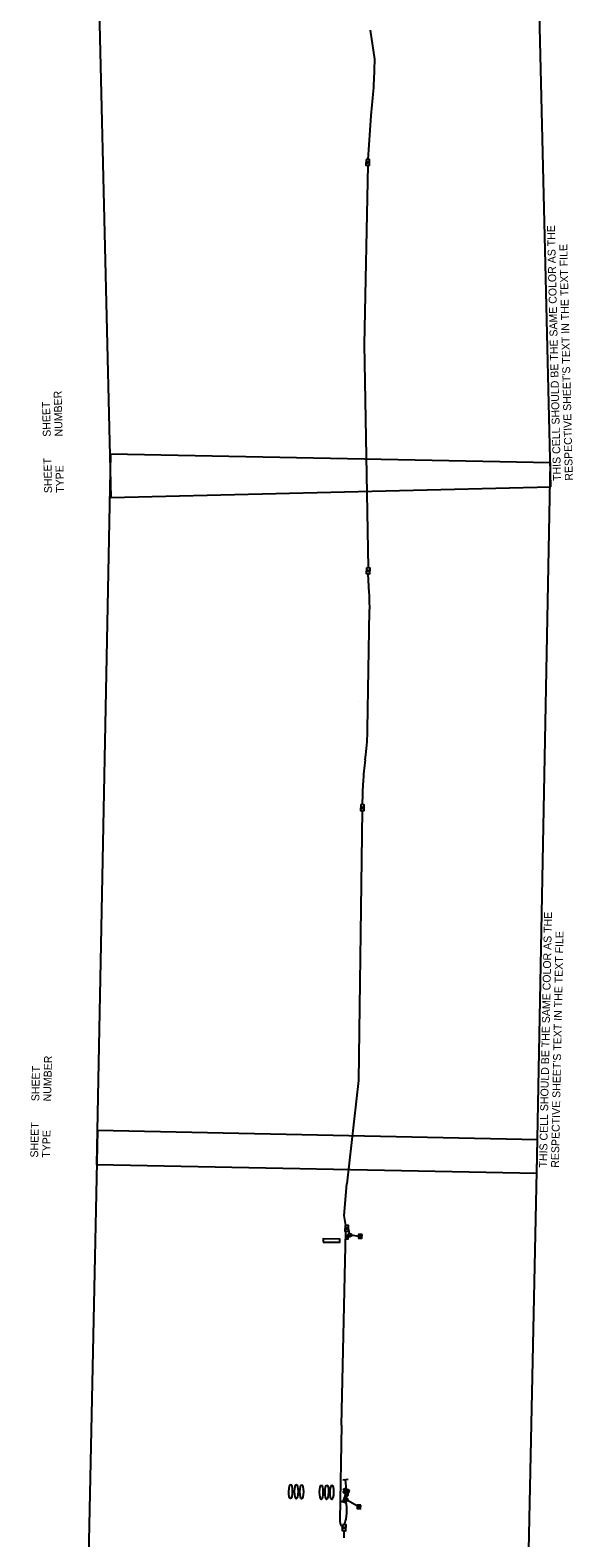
# Model space of a CAD drawing. Extents: x 601462 to 605493, y 331960 to 402715.
# Drawn here: x 603678 to 604880, y 344593 to 347935 of the extents above; entities that cross this region are included whole.
import ezdxf

# ---------------------------------------------------------------- set-up
doc = ezdxf.new("R2010")
doc.units = 0
for name, color, linetype in [('E_FTMS', 7, 'Continuous'), ('P_FTMS', 7, 'Continuous'), ('P_FTMSConduit', 7, 'Continuous'), ('P_MISC_TXT_2A (Construction)', 7, 'Continuous'), ('P_MISC_TXT_2B (Construction)', 7, 'Continuous')]:
    doc.layers.add(name, color=color, linetype=linetype)

# ---------------------------------------------------------------- blocks, each defined once
blk = doc.blocks.new('FMD')
at = {"layer": 'P_FTMS'}
for p, q in [((17, 18), (-17, 18)), ((-16, 16), (-16, 18)), ((16, 16), (-16, 16)), ((-15, 15), (-15, 20)), ((15, 19), (-15, 19)), ((15, 15), (-15, 15)), ((14, 20), (-14, 20)), ((13, 22), (-13, 22)), ((-13, 13), (-13, 21)), ((13, 13), (-13, 13)), ((-12, 12), (-12, 23)), ((12, 12), (-12, 12)), ((11, 23), (-11, 23)), ((10, 25), (-10, 25)), ((-10, 10), (-10, 24)), ((10, 10), (-10, 10)), ((-9, 9), (-9, 26)), ((9, 9), (-9, 9)), ((8, 26), (-8, 26)), ((7, 28), (-7, 28)), ((-7, 7), (-7, 27)), ((7, 7), (-7, 7)), ((-6, 6), (-6, 29)), ((6, 6), (-6, 6)), ((5, 29), (-5, 29)), ((4, 31), (-4, 31)), ((-4, 4), (-4, 30)), ((4, 4), (-4, 4)), ((-3, 3), (-3, 32)), ((3, 3), (-3, 3)), ((2, 32), (-2, 32)), ((1, 34), (-1, 34)), ((-1, 1), (-1, 33)), ((1, 1), (-1, 1)), ((0, 0), (0, 34)), ((1, 1), (1, 33)), ((3, 3), (3, 32)), ((4, 4), (4, 30)), ((6, 6), (6, 29)), ((7, 7), (7, 27)), ((9, 9), (9, 26)), ((10, 10), (10, 24)), ((12, 12), (12, 23)), ((13, 13), (13, 21)), ((15, 15), (15, 20)), ((16, 16), (16, 18))]:
    blk.add_line(p, q, dxfattribs=at)
blk.add_lwpolyline([(-17, 17), (0, 34), (17, 17), (0, 0)], close=True, dxfattribs=at)
blk = doc.blocks.new('FMB')
at = {"layer": 'P_FTMS'}
for p, q in [((24, -24), (-24, 24)), ((-24, -24), (24, 24))]:
    blk.add_line(p, q, dxfattribs=at)
blk.add_lwpolyline([(24, -24), (24, 24), (-24, 24), (-24, -24)], close=True, dxfattribs=at)
blk = doc.blocks.new('_U218')
at = {"layer": 'P_FTMS'}
for points in [[(-15, -7), (7, -15), (0, 0)], [(15, 7), (-7, 15), (0, 0)]]:
    blk.add_lwpolyline(points, close=True, dxfattribs=at)
at = {"layer": 'P_FTMS', "xscale": 0.4713263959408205, "yscale": 0.4713263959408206, "rotation": 70.39802054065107}
blk.add_blockref('FMB', (0, 0), dxfattribs=at)
blk = doc.blocks.new('FMB_1')
at = {"layer": 'P_FTMS'}
for p, q in [((24, -24), (-24, 24)), ((-24, -24), (24, 24))]:
    blk.add_line(p, q, dxfattribs=at)
blk.add_lwpolyline([(24, -24), (24, 24), (-24, 24), (-24, -24)], close=True, dxfattribs=at)
blk = doc.blocks.new('FTMS_FCV')
at = {"layer": 'P_FTMS'}
blk.add_line((13, 16), (1, -22), dxfattribs=at)
blk.add_lwpolyline([(39, 24), (-39, 24), (-39, -24), (39, -24)], close=True, dxfattribs=at)
blk.add_lwpolyline([(-12, 16), (1, -22)], dxfattribs=at)
blk = doc.blocks.new('_U256')
at = {"layer": 'P_FTMS'}
for points in [[(-15, -7), (7, -15), (0, 0)], [(15, 7), (-7, 15), (0, 0)]]:
    blk.add_lwpolyline(points, close=True, dxfattribs=at)
at = {"layer": 'P_FTMS', "xscale": 0.4713263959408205, "yscale": 0.4713263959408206, "rotation": 70.39802054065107}
blk.add_blockref('FMB', (0, 0), dxfattribs=at)
blk = doc.blocks.new('FTMS_FERA')
at = {"layer": 'P_FTMS'}
for p, q in [((-65, 37), (-65, -37)), ((65, 0), (-65, 0))]:
    blk.add_line(p, q, dxfattribs=at)

msp = doc.modelspace()

# ---------------------------------------------------------------- linework, layer by layer
at = {"layer": 'P_FTMS'}
for p, q in [((604376.9, 344696.1), (604381.5, 344700.6)), ((604376.9, 344696.4), (604381.2, 344700.6)), ((604376.9, 344696.8), (604380.9, 344700.6)), ((604376.9, 344697.1), (604380.5, 344700.6)), ((604381.1, 344692.6), (604376.9, 344696.9)), ((604380.8, 344692.6), (604376.9, 344696.6)), ((604380.4, 344692.7), (604376.9, 344696.2)), ((604377, 344695.8), (604381.8, 344700.5)), ((604377, 344697.5), (604380.1, 344700.5)), ((604377, 344695.6), (604382.1, 344700.4)), ((604381.7, 344692.7), (604377, 344697.5)), ((604381.4, 344692.7), (604377, 344697.2)), ((604380, 344692.7), (604377, 344695.8)), ((604377.1, 344695.3), (604382.3, 344700.3)), ((604382, 344692.8), (604377.1, 344697.8)), ((604379.5, 344692.9), (604377.1, 344695.3)), ((604377.2, 344698), (604379.6, 344700.4)), ((604377.2, 344695.1), (604382.6, 344700.2)), ((604382.2, 344692.9), (604377.2, 344698)), ((604377.3, 344694.8), (604382.8, 344700.1)), ((604382.5, 344692.9), (604377.3, 344698.3)), ((604377.4, 344698.6), (604379, 344700.1)), ((604382.7, 344693.1), (604377.4, 344698.5)), ((604378.9, 344693.2), (604377.4, 344694.7)), ((604377.5, 344694.6), (604383, 344700)), ((604382.9, 344693.2), (604377.5, 344698.7)), ((604377.6, 344694.4), (604383.2, 344699.9)), ((604383.1, 344693.3), (604377.6, 344698.9)), ((604377.7, 344694.2), (604383.4, 344699.7)), ((604383.3, 344693.4), (604377.8, 344699.1)), ((604377.9, 344694), (604383.6, 344699.6)), ((604383.5, 344693.6), (604377.9, 344699.3)), ((604378, 344693.8), (604383.8, 344699.4)), ((604383.7, 344693.8), (604378.1, 344699.5)), ((604378.2, 344693.7), (604383.9, 344699.2)), ((604383.8, 344693.9), (604378.3, 344699.6)), ((604378.4, 344693.5), (604384.1, 344699)), ((604384, 344694.1), (604378.5, 344699.8)), ((604378.6, 344693.4), (604384.2, 344698.8)), ((604384.2, 344694.3), (604378.7, 344699.9)), ((604378.8, 344693.2), (604384.4, 344698.6)), ((604384.3, 344694.5), (604378.9, 344700.1)), ((604379, 344693.1), (604384.5, 344698.4)), ((604384.4, 344694.7), (604379.1, 344700.2)), ((604379.2, 344693), (604384.6, 344698.2)), ((604384.5, 344695), (604379.3, 344700.3)), ((604379.5, 344692.9), (604384.7, 344697.9)), ((604384.6, 344695.2), (604379.6, 344700.4)), ((604379.7, 344692.8), (604384.7, 344697.7)), ((604384.7, 344695.4), (604379.8, 344700.5)), ((604380, 344692.7), (604384.8, 344697.4)), ((604384.8, 344695.7), (604380.1, 344700.5)), ((604380.3, 344692.7), (604384.9, 344697.1)), ((604384.8, 344696), (604380.4, 344700.6)), ((604380.6, 344692.6), (604384.9, 344696.8)), ((604384.9, 344696.3), (604380.7, 344700.6)), ((604380.9, 344692.6), (604384.9, 344696.5)), ((604384.9, 344696.6), (604381, 344700.6)), ((604381.3, 344692.6), (604384.9, 344696.1)), ((604384.9, 344697), (604381.4, 344700.6)), ((604381.7, 344692.7), (604384.8, 344695.7)), ((604384.8, 344697.4), (604381.8, 344700.5)), ((604382.2, 344692.8), (604384.6, 344695.2)), ((604384.7, 344697.9), (604382.3, 344700.4)), ((604382.8, 344693.1), (604384.3, 344694.6)), ((604384.4, 344698.5), (604382.9, 344700.1))]:
    msp.add_line(p, q, dxfattribs=at)
msp.add_lwpolyline([(604327.5, 345248.8), (604364.5, 345248.2), (604364.6, 345255.1), (604327.6, 345255.7)], close=True, dxfattribs=at)
for centre, radius in [((604386.4, 345264.3), 3.75), ((604380.9, 344696.6), 4), ((604378.1, 344677.6), 3.75)]:
    msp.add_circle(centre, radius, dxfattribs=at)
for centre, start, end in [((604386, 345268.8), 222.4831, 328.7387), ((604386.9, 345259.8), 42.4831, 148.7387), ((604377.6, 344682.1), 222.4831, 328.7387), ((604378.5, 344673.1), 42.4831, 148.7387)]:
    msp.add_arc(centre, 3.75, start, end, dxfattribs=at)
for centre in [(604255.2, 344696.2), (604267.9, 344695.8), (604279.7, 344695.4), (604323.2, 344694.5), (604335.3, 344694.3), (604346.6, 344694.2)]:
    msp.add_ellipse(centre, major_axis=(0.2, 16), ratio=0.23471, dxfattribs=at)
at = {"layer": 'P_FTMSConduit'}
for p, q in [((604441.6, 347870.4), (604432.3, 347934.9)), ((604427.1, 347648.3), (604433.5, 347746)), ((604419.2, 347238.4), (604426.7, 347635.5)), ((604427.5, 346742.9), (604419.2, 347238.4)), ((604429.5, 346688.1), (604426.9, 346730.1)), ((604425.9, 346385.9), (604430.3, 346648.8)), ((604405.2, 346445.8), (604405.2, 346445.8)), ((604405.2, 346445.8), (604405.2, 346445.8)), ((604420.1, 346317.6), (604421.6, 346328.8)), ((604414.6, 346218.2), (604416, 346266.8)), ((604414, 346205.4), (604405.6, 345607)), ((604405.6, 345607), (604379.9, 345377.5)), ((604367.7, 344842.6), (604377.5, 345273)), ((604378.3, 345260.5), (604383.2, 345266.2)), ((604381.3, 345261.2), (604383.7, 345261.8)), ((604382.8, 345258.1), (604384.5, 345261.1)), ((604385.7, 345268), (604383.6, 345279)), ((604405.5, 345261.4), (604390.2, 345263.9)), ((604327.6, 345255.7), (604327.5, 345248.8)), ((604327.5, 345248.8), (604364.5, 345248.2)), ((604364.6, 345255.1), (604327.6, 345255.7)), ((604364.5, 345248.2), (604364.6, 345255.1)), ((604378, 344681.5), (604379.7, 344688.1)), ((604378.1, 344681.3), (604380.8, 344686.6)), ((604403.1, 344663.5), (604381.3, 344675.8))]:
    msp.add_line(p, q, dxfattribs=at)
for points in [[(604377.8, 345285.7), (604374, 345307.7), (604379.9, 345377.5)], [(604367.7, 344842.6), (604364, 344633.1)], [(604367.6, 344619.8), (604370, 344615.8)]]:
    msp.add_lwpolyline(points, dxfattribs=at)
for centre, radius, start, end in [((603357.2, 347878.4), 1084.4, 352.9879, 359.5787), ((603930.4, 346657.3), 500, 359.0251, 3.5273), ((603925.9, 346394.4), 500, 352.4524, 359.0251), ((604915.8, 346251.9), 500, 172.4524, 178.2991), ((604289.7, 344653.8), 90.3, 339.4924, 12.9834), ((604389, 344632.6), 25, 178.9985, 210.8217), ((603933.9, 344597.7), 439.9, 359.4129, 1.5131)]:
    msp.add_arc(centre, radius, start, end, dxfattribs=at)
at = {"layer": 'P_MISC_TXT_2A (Construction)'}
for points in [[(604831.9, 346922.5), (604794.2, 348497), (603819.5, 348473.7), (603857.2, 346899.1)], [(604768.7, 343901), (604801.9, 345475.6), (603827.1, 345496.2), (603793.9, 343921.5)]]:
    msp.add_lwpolyline(points, close=True, dxfattribs=at)
at = {"layer": 'P_MISC_TXT_2B (Construction)'}
msp.add_lwpolyline([(604800.4, 345401.4), (604831.2, 346976.1), (603856.4, 346995.2), (603825.6, 345420.5)], close=True, dxfattribs=at)

# ---------------------------------------------------------------- block references
at = {"layer": 'E_FTMS', "xscale": 0.16404166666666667, "yscale": 0.1640416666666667, "rotation": 89.02022232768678}
msp.add_blockref('FMB_1', (604406.5, 344661.8), dxfattribs=at)
at = {"layer": 'P_FTMS'}
for name, p, xscale, yscale, rotation in [('FTMS_FCV', (604426.1, 347641.9), 0.1640416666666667, 0.16404166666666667, 87.23689791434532), ('FTMS_FCV', (604427.2, 346736.5), 0.1640416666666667, 0.16404166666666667, 87.23689791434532), ('FTMS_FCV', (604414.3, 346211.8), 0.1640416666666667, 0.16404166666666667, 87.23689791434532), ('FTMS_FCV', (604379.6, 345279.2), 0.1640416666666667, 0.16404166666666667, 87.23689791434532), ('_U218', (604380.5, 345258.2), 0.19684999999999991, 0.19684999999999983, 108.48808927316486), ('FMB_1', (604409.5, 345261.4), 0.16404166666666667, 0.1640416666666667, 89.02022232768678), ('FTMS_FERA', (604374.7, 344683.5), 0.1640416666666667, 0.16404166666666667, 69.9653139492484), ('FTMS_FERA', (604378.2, 344711.1), 0.1640416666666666, 0.16404166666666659, -83.64704646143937), ('FMD', (604372, 344694.4), 0.16404166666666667, 0.16404166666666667, -94.10713576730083), ('FMD', (604372.4, 344700), 0.16404166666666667, 0.16404166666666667, -94.10713576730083), ('_U256', (604380.8, 344690.4), 0.19684999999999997, 0.19685, -160.22559933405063), ('FTMS_FCV', (604374, 344615.7), 0.1640416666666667, 0.16404166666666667, 87.23689791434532)]:
    msp.add_blockref(name, p, dxfattribs=dict(at, xscale=xscale, yscale=yscale, rotation=rotation))

# ---------------------------------------------------------------- texts
at = {"layer": 'P_MISC_TXT_2A (Construction)'}
for s, p in [('THIS CELL SHOULD BE THE SAME COLOR AS THE', (604854.2, 346936)), ("RESPECTIVE SHEET'S TEXT IN THE TEXT FILE", (604880.5, 346936.6)), ('NUMBER', (603750.3, 347034.5)), ('SHEET', (603724, 347033.9)), ('SHEET', (603727, 346908.9)), ('TYPE', (603753.3, 346909.6))]:
    msp.add_text(s, height=17.5, rotation=91.3726, dxfattribs=at).set_placement(p)
at = {"layer": 'P_MISC_TXT_2B (Construction)'}
for s, p in [('THIS CELL SHOULD BE THE SAME COLOR AS THE', (604823.2, 345413.9)), ("RESPECTIVE SHEET'S TEXT IN THE TEXT FILE", (604849.5, 345413.4)), ('NUMBER', (603724.7, 345560.4)), ('SHEET', (603698.4, 345560.9)), ('SHEET', (603696, 345436)), ('TYPE', (603722.2, 345435.5))]:
    msp.add_text(s, height=17.5, rotation=88.8774, dxfattribs=at).set_placement(p)

doc.saveas('drawing.dxf')
